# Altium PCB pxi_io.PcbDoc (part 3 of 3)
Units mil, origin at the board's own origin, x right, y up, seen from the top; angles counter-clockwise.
Board outline 6300 x 3935 mil, 2 copper layers (Top Layer, Bottom Layer); 271 components, 388 nets, 1544 pads, 249 vias.
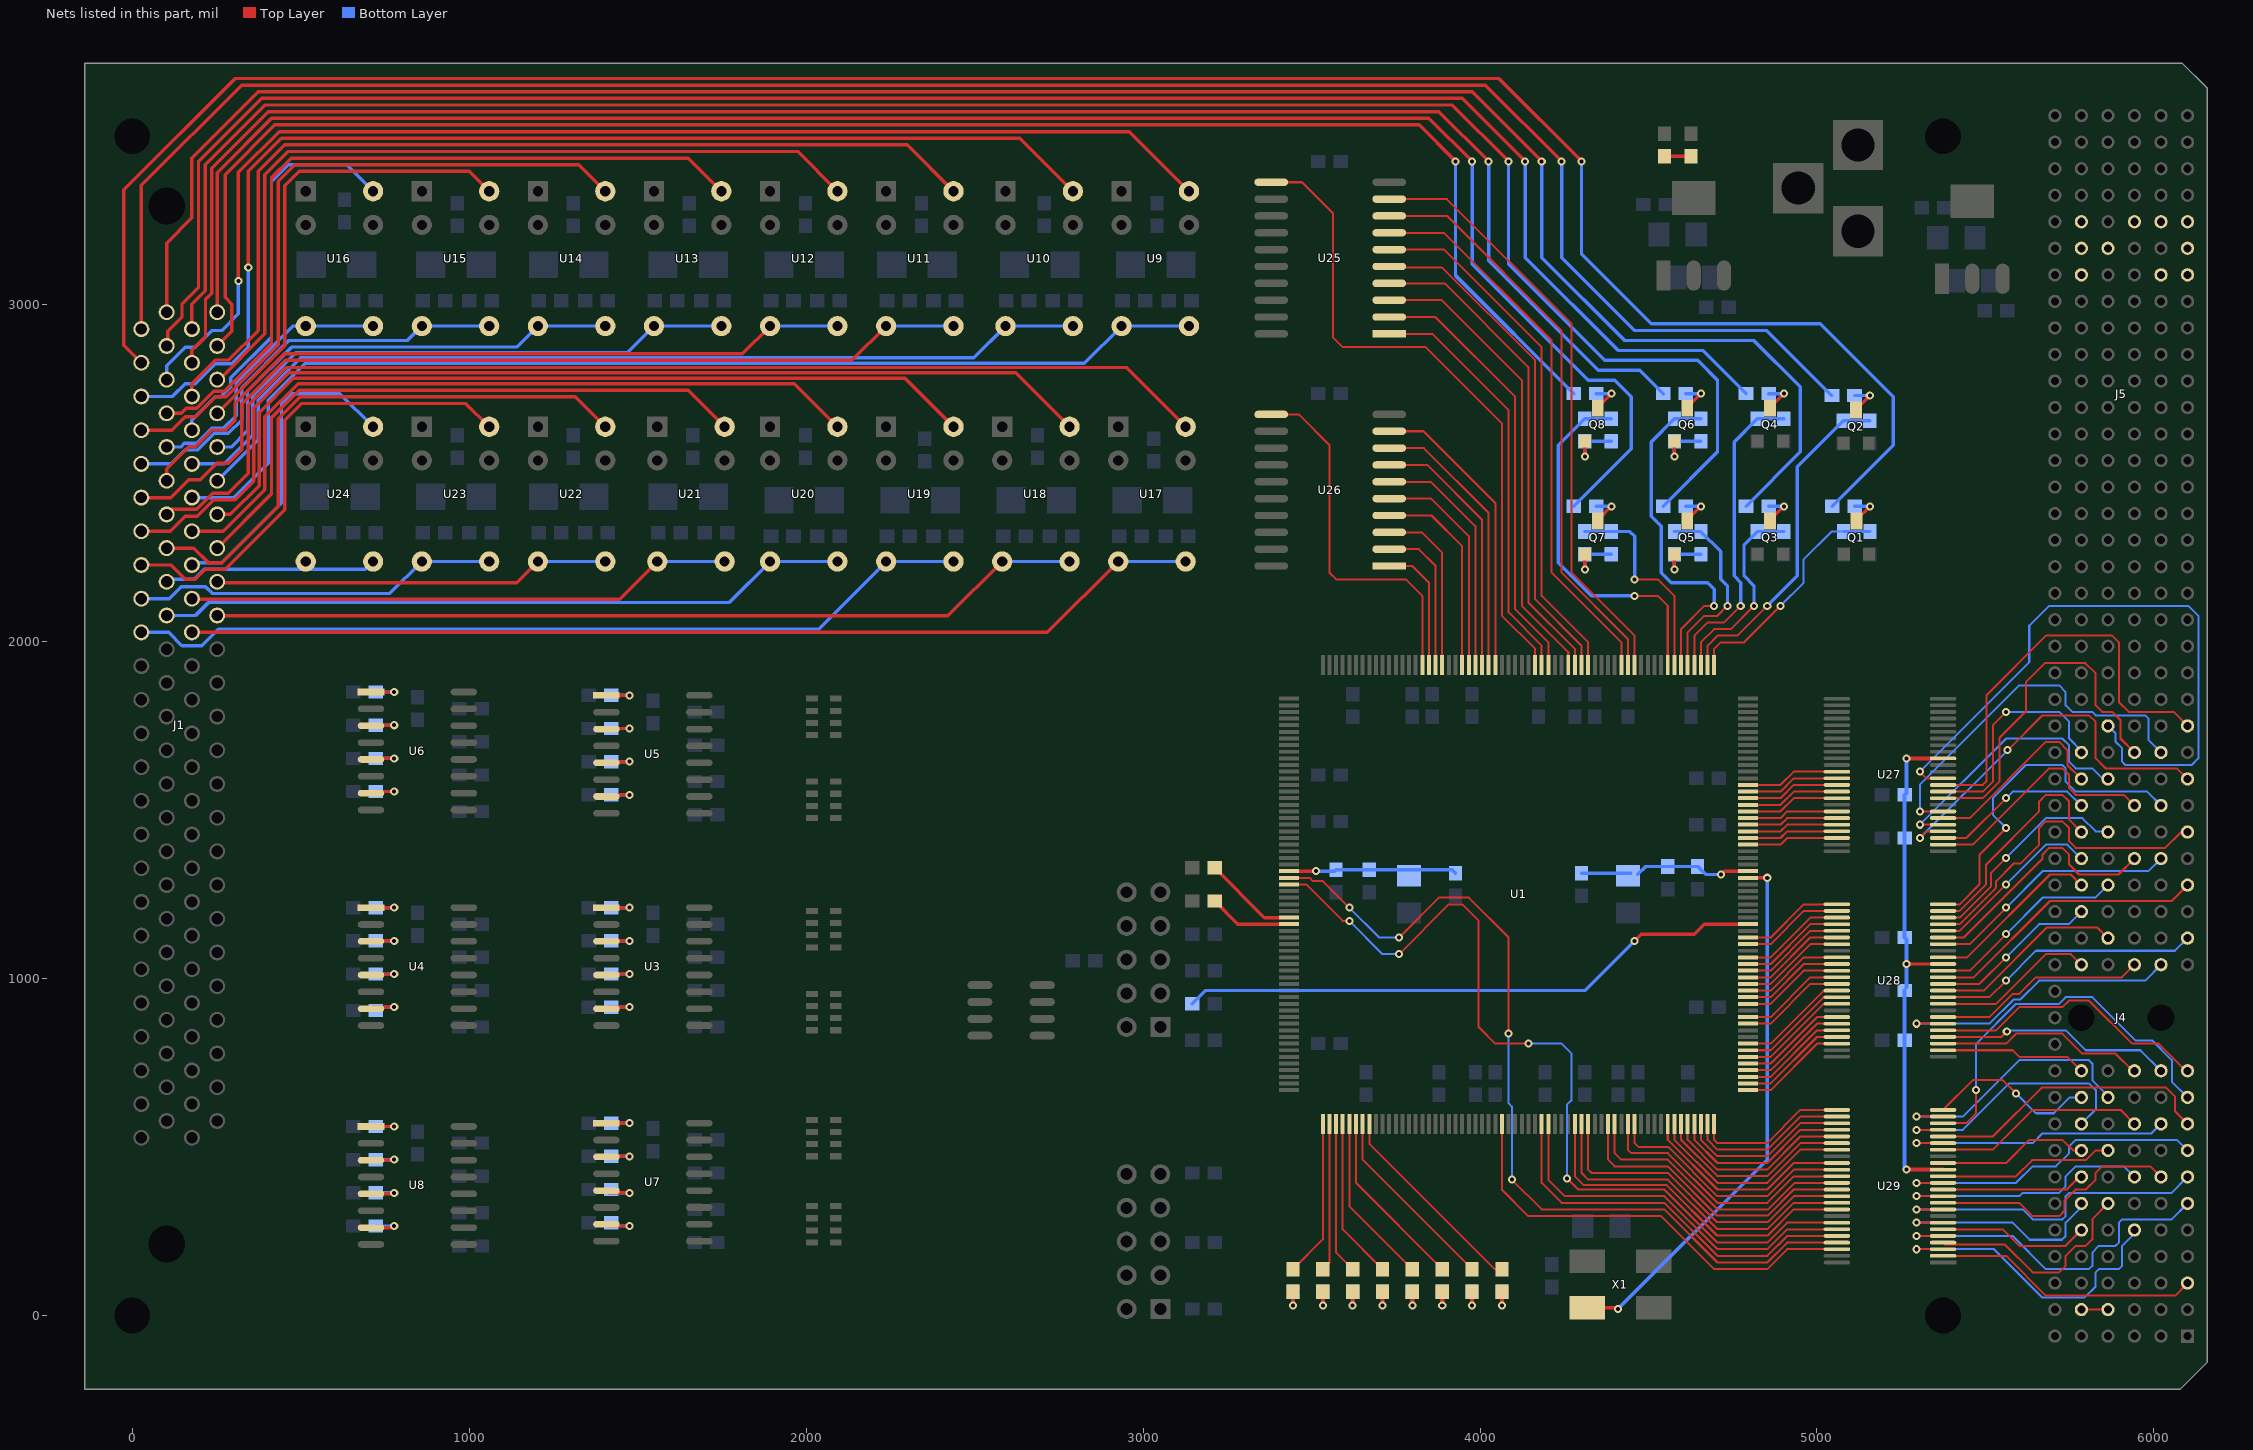
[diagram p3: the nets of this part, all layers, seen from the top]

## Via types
v1: diameter 24, hole 12, Top Layer to Bottom Layer, 241 vias
v2: diameter 36, hole 18, Top Layer to Bottom Layer, 7 vias
v3: diameter 24, hole 12, Top Layer to Bottom Layer, tented bottom, 1 vias

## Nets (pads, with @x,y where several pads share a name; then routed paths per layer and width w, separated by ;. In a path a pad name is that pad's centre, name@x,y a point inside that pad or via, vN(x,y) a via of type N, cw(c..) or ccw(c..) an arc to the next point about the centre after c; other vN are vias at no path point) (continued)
NetC85_1: C85.1 Q5.2 R108.2 | length 169.6
  Top Layer w10: v1(4576.77,2214.57) 4576.77,2258.93 Q5.2@4577.63,2259.79
  Bottom Layer w10: v1(4576.77,2214.57) C85.1@4576.77,2259.84 R108.2@4655.51,2259.84
NetC86_1: C86.1 Q6.2 R110.2 | length 169.6
  Top Layer w10: v1(4576.77,2549.21) 4576.77,2593.57 Q6.2@4577.63,2594.43
  Bottom Layer w10: v1(4576.77,2549.21) C86.1@4576.77,2594.49 R110.2@4655.51,2594.49
NetC87_1: C87.1 Q7.2 R112.2 | length 169.6
  Top Layer w10: v1(4311.02,2214.57) 4311.02,2258.93 Q7.2@4311.88,2259.79
  Bottom Layer w10: v1(4311.02,2214.57) C87.1@4311.02,2259.84 R112.2@4389.76,2259.84
NetC88_1: C88.1 Q8.2 R114.2 | length 169.6
  Top Layer w10: v1(4311.02,2549.21) 4311.02,2593.57 Q8.2@4311.88,2594.43
  Bottom Layer w10: v1(4311.02,2549.21) C88.1@4311.02,2594.49 R114.2@4389.76,2594.49
NetDS1_1: DS1.1 U1.68 | length 606.5
  Top Layer w6: U1.68@3671.26,568.9 3671.26,510.39 4043.85,137.8 DS1.1@4064.96,137.8
NetDS1_2: DS1.2 R120.1 | length 82.7
  Top Layer w12: v1(4064.96,29.53) DS1.2@4064.96,70.87
  Bottom Layer w10: v1(4064.96,29.53) R120.1@4064.96,70.87
NetDS2_1: DS2.1 U1.67 | length 565.6
  Top Layer w6: U1.67@3651.57,568.9 3651.57,462.6 DS2.1@3976.38,137.8
NetDS2_2: DS2.2 R121.1 | length 82.7
  Top Layer w12: v1(3976.38,29.53) DS2.2@3976.38,70.87
  Bottom Layer w10: v1(3976.38,29.53) R121.1@3976.38,70.87
NetDS3_1: DS3.1 U1.66 | length 537.1
  Top Layer w6: U1.66@3631.89,568.9 3631.89,393.7 DS3.1@3887.8,137.8
NetDS3_2: DS3.2 R122.1 | length 82.7
  Top Layer w12: v1(3887.8,29.53) DS3.2@3887.8,70.87
  Bottom Layer w10: v1(3887.8,29.53) R122.1@3887.8,70.87
NetDS4_1: DS4.1 U1.65 | length 508.6
  Top Layer w6: U1.65@3612.2,568.9 3612.2,324.8 DS4.1@3799.21,137.8
NetDS4_2: DS4.2 R123.1 | length 82.7
  Top Layer w12: v1(3799.21,29.53) DS4.2@3799.21,70.87
  Bottom Layer w10: v1(3799.21,29.53) R123.1@3799.21,70.87
NetDS5_1: DS5.1 U1.64 | length 480
  Top Layer w6: U1.64@3592.52,568.9 3592.52,255.91 DS5.1@3710.63,137.8
NetDS5_2: DS5.2 R124.1 | length 82.7
  Top Layer w12: v1(3710.63,29.53) DS5.2@3710.63,70.87
  Bottom Layer w10: v1(3710.63,29.53) R124.1@3710.63,70.87
NetDS6_1: DS6.1 U1.63 | length 451.5
  Top Layer w6: U1.63@3572.83,568.9 3572.83,187.01 DS6.1@3622.05,137.8
NetDS6_2: DS6.2 R125.1 | length 82.7
  Top Layer w12: v1(3622.05,29.53) DS6.2@3622.05,70.87
  Bottom Layer w10: v1(3622.05,29.53) R125.1@3622.05,70.87
NetDS7_1: DS7.1 U1.62 | length 439.3
  Top Layer w6: DS7.1@3533.46,137.8 3553.15,157.48 U1.62@3553.15,568.9
NetDS7_2: DS7.2 R126.1 | length 82.7
  Top Layer w10: v1(3533.46,29.53) DS7.2@3533.46,70.87
  Bottom Layer w10: v1(3533.46,29.53) R126.1@3533.46,70.87
NetDS8_1: DS8.1 U1.61 | length 467.8
  Top Layer w6: DS8.1@3444.88,137.8 3533.46,226.38 U1.61@3533.46,568.9
NetDS8_2: DS8.2 R127.1 | length 82.7
  Top Layer w10: v1(3444.88,29.53) DS8.2@3444.88,70.87
  Bottom Layer w10: v1(3444.88,29.53) R127.1@3444.88,70.87
NetDS9_2: DS9.2 R140.2 | length 78.7
  Top Layer w10: R140.2@4547.24,3440.94 DS9.2@4625.98,3440.94
NetJ4_d2: J4.D2 J4.E2 | length 78.7
  Top Layer w6: J4.E2@5784.65,17.72 J4.D2@5863.39,17.72
NetQ1_1: Q1.1 R101.1 | length 105.4
  Top Layer w10: Q1.1@5117,2358.21 5117,2361.09 v1(5157.48,2401.57)
  Bottom Layer w10: R101.1@5112.2,2401.57 v1(5157.48,2401.57)
NetQ2_1: Q2.1 R103.1 | length 105.4
  Top Layer w10: Q2.1@5116.14,2687.01 5116.14,2689.89 v1(5156.62,2730.37)
  Bottom Layer w10: R103.1@5111.35,2730.37 v1(5156.62,2730.37)
NetQ3_1: Q3.1 R105.1 | length 105.4
  Top Layer w10: Q3.1@4861.09,2358.21 4861.09,2361.09 v1(4901.57,2401.57)
  Bottom Layer w10: R105.1@4856.3,2401.57 v1(4901.57,2401.57)
NetQ4_1: Q4.1 R107.1 | length 105.4
  Top Layer w10: Q4.1@4861.09,2692.86 4861.09,2695.74 v1(4901.57,2736.22)
  Bottom Layer w10: R107.1@4856.3,2736.22 v1(4901.57,2736.22)
NetQ5_1: Q5.1 R109.1 | length 105.4
  Top Layer w10: Q5.1@4615.03,2358.21 4615.03,2361.09 v1(4655.51,2401.57)
  Bottom Layer w10: R109.1@4610.24,2401.57 v1(4655.51,2401.57)
NetQ6_1: Q6.1 R111.1 | length 105.4
  Top Layer w10: Q6.1@4615.03,2692.86 4615.03,2695.74 v1(4655.51,2736.22)
  Bottom Layer w10: R111.1@4610.24,2736.22 v1(4655.51,2736.22)
NetQ7_1: Q7.1 R113.1 | length 101
  Top Layer w10: Q7.1@4350.39,2362.2 v1(4389.76,2401.57)
  Bottom Layer w10: R113.1@4344.49,2401.57 v1(4389.76,2401.57)
NetQ8_1: Q8.1 R115.1 | length 105.4
  Top Layer w10: Q8.1@4349.28,2692.86 4349.28,2695.74 v1(4389.76,2736.22)
  Bottom Layer w10: R115.1@4344.49,2736.22 v1(4389.76,2736.22)
NetR9_1: R9.1 U1.34 | length 281.6
  Top Layer w10: R9.1@3212.6,1328.74 3360.24,1181.1 U1.34@3433.07,1181.1
NetR10_1: R10.1 U1.35 | length 249
  Top Layer w10: R10.1@3212.6,1230.32 3281.5,1161.42 U1.35@3433.07,1161.42
NetR11_2: R11.2 U3.7 | length 126
  Top Layer w10: U3.7@1407.48,910.63 1412.2,915.35 v1(1476.38,915.35)
  Bottom Layer w10: R11.2@1421.26,915.35 v1(1476.38,915.35)
NetR12_2: R12.2 U3.5 | length 125.3
  Top Layer w10: U3.5@1407.48,1010.63 1410.63,1013.78 v1(1476.38,1013.78)
  Bottom Layer w10: R12.2@1421.26,1013.78 v1(1476.38,1013.78)
NetR13_2: R13.2 U3.3 | length 124.7
  Top Layer w10: U3.3@1407.48,1110.63 1409.05,1112.2 v1(1476.38,1112.2)
  Bottom Layer w10: R13.2@1421.26,1112.2 v1(1476.38,1112.2)
NetR14_2: R14.2 U3.1 | length 124
  Top Layer w10: U3.1@1407.48,1210.63 v1(1476.38,1210.63)
  Bottom Layer w10: R14.2@1421.26,1210.63 v1(1476.38,1210.63)
NetR19_2: R19.2 U4.7 | length 130
  Top Layer w10: U4.7@708.66,910.63 713.39,915.35 v1(777.56,915.35)
  Bottom Layer w10: R19.2@722.44,905.51 732.28,915.35 v1(777.56,915.35)
NetR20_2: R20.2 U4.5 | length 125.3
  Top Layer w10: U4.5@708.66,1010.63 711.81,1013.78 v1(777.56,1013.78)
  Bottom Layer w10: R20.2@722.44,1013.78 v1(777.56,1013.78)
NetR21_2: R21.2 U4.3 | length 124.7
  Top Layer w10: U4.3@708.66,1110.63 710.24,1112.2 v1(777.56,1112.2)
  Bottom Layer w10: R21.2@722.44,1112.2 v1(777.56,1112.2)
NetR22_2: R22.2 U4.1 | length 124
  Top Layer w10: U4.1@708.66,1210.63 v1(777.56,1210.63)
  Bottom Layer w10: R22.2@722.44,1210.63 v1(777.56,1210.63)
NetR27_2: R27.2 U5.7 | length 119.3
  Top Layer w10: U5.7@1412.2,1545.28 v1(1476.38,1545.28)
  Bottom Layer w10: R27.2@1421.26,1545.28 v1(1476.38,1545.28)
NetR28_2: R28.2 U5.5 | length 120.9
  Top Layer w10: U5.5@1410.63,1643.7 v1(1476.38,1643.7)
  Bottom Layer w10: R28.2@1421.26,1643.7 v1(1476.38,1643.7)
NetR29_2: R29.2 U5.3 | length 124.7
  Top Layer w10: U5.3@1407.48,1740.55 1409.06,1742.13 v1(1476.38,1742.13)
  Bottom Layer w10: R29.2@1421.26,1742.13 v1(1476.38,1742.13)
NetR30_2: R30.2 U5.1 | length 124
  Top Layer w10: U5.1@1407.48,1840.55 v1(1476.38,1840.55)
  Bottom Layer w10: R30.2@1421.26,1840.55 v1(1476.38,1840.55)
NetR35_2: R35.2 U6.7 | length 126
  Top Layer w10: U6.7@708.66,1550.39 713.39,1555.12 v1(777.56,1555.12)
  Bottom Layer w10: R35.2@722.44,1555.12 v1(777.56,1555.12)
NetR36_2: R36.2 U6.5 | length 125.3
  Top Layer w10: U6.5@708.66,1650.39 711.81,1653.54 v1(777.56,1653.54)
  Bottom Layer w10: R36.2@722.44,1653.54 v1(777.56,1653.54)
NetR37_2: R37.2 U6.3 | length 124.7
  Top Layer w10: U6.3@708.66,1750.39 710.24,1751.97 v1(777.56,1751.97)
  Bottom Layer w10: R37.2@722.44,1751.97 v1(777.56,1751.97)
NetR38_2: R38.2 U6.1 | length 124
  Top Layer w10: U6.1@708.66,1850.39 v1(777.56,1850.39)
  Bottom Layer w10: R38.2@722.44,1850.39 v1(777.56,1850.39)
NetR45_2: R45.2 U7.7 | length 130.2
  Top Layer w10: U7.7@1407.48,270.87 1412.6,265.75 v1(1476.38,265.75)
  Bottom Layer w10: R45.2@1421.26,275.59 1431.1,265.75 v1(1476.38,265.75)
NetR48_2: R48.2 U7.5 | length 130.9
  Top Layer w10: U7.5@1407.48,370.87 1414.17,364.17 v1(1476.38,364.17)
  Bottom Layer w10: R48.2@1421.26,374.02 1431.1,364.17 v1(1476.38,364.17)
NetR51_2: R51.2 U7.3 | length 124.7
  Top Layer w10: U7.3@1407.48,470.87 1409.06,472.44 v1(1476.38,472.44)
  Bottom Layer w10: R51.2@1421.26,472.44 v1(1476.38,472.44)
NetR54_2: R54.2 U7.1 | length 124
  Top Layer w10: U7.1@1407.48,570.87 v1(1476.38,570.87)
  Bottom Layer w10: R54.2@1421.26,570.87 v1(1476.38,570.87)
NetR61_2: R61.2 U8.7 | length 126
  Top Layer w10: U8.7@708.66,261.02 772.83,261.02 v1(777.56,265.75)
  Bottom Layer w10: R61.2@722.44,265.75 v1(777.56,265.75)
NetR64_2: R64.2 U8.5 | length 125.3
  Top Layer w10: U8.5@708.66,361.02 774.41,361.02 v1(777.56,364.17)
  Bottom Layer w10: R64.2@722.44,364.17 v1(777.56,364.17)
NetR67_2: R67.2 U8.3 | length 122.4
  Top Layer w10: U8.3@708.66,461.02 v1@775.98,461.02
  Bottom Layer w10: R67.2@722.44,462.6 v1(777.56,462.6)
NetR70_2: R70.2 U8.1 | length 124
  Top Layer w10: U8.1@708.66,561.02 v1(777.56,561.02)
  Bottom Layer w10: R70.2@722.44,561.02 v1(777.56,561.02)
NetU1_153: U1.153 X1.3 | length 1613
  Top Layer w10: X1.3@4317.98,23.1 4406.03,23.1 v1(4409.45,19.69) ; U1.153@4795.28,1299.21 v1(4852.36,1299.21)
  Bottom Layer w10: v1(4409.45,19.69) 4852.36,462.6 v1(4852.36,1299.21)
NSTATUS: R8.2 U1.146 | length 1747.5
  Top Layer w10: v1(4458.66,1112.2) 4478.35,1131.89 4635.83,1131.89 4665.35,1161.42 U1.146@4795.28,1161.42
  Bottom Layer w10: R8.2@3145.67,925.2 3185.04,964.57 4311.02,964.57 v1(4458.66,1112.2)
O5_1_A: J1.39 U9.5 U9.6 | length 3279.5
  Bottom Layer w10: J1.39@177.17,2427.56 301.57,2427.56 403.54,2529.53 403.54,2716.54 513.28,2826.28 2825.88,2826.28 U9.5@2936.22,2936.61 U9.6@3136.22,2936.61
O5_1_B: J1.96 U9.10 | length 3682.7
  Top Layer w10: v1(314.96,3070.87) 314.96,3392.73 436.01,3513.78 2959.06,3513.78 U9.10@3136.22,3336.61
  Bottom Layer w10: J1.96@102.17,2777.56 102.17,2818.7 157.48,2874.02 187.01,2874.02 236.22,2923.23 265.75,2923.23 314.96,2972.44 v1(314.96,3070.87)
O5_2_A: J1.40 U10.5 U10.6 | length 2798.3
  Bottom Layer w10: J1.40@252.17,2477.56 374.02,2599.41 374.02,2716.54 499.76,2842.28 2497.39,2842.28 U10.5@2591.73,2936.61 U10.6@2791.73,2936.61
O5_2_B: J1.95 U10.10 | length 3452.9
  Top Layer w10: v1(344.49,3110.24) 344.49,3395.67 442.91,3494.09 2634.25,3494.09 U10.10@2791.73,3336.61
  Bottom Layer w10: J1.95@27.17,2727.56 119.29,2727.56 157.48,2765.75 187.01,2765.75 246.06,2824.8 295.28,2824.8 344.49,2874.02 v1(344.49,3110.24)
O5_3_A: J1.89 U11.5 U11.6 | length 2700.7
  Top Layer w10: J1.89@27.17,2427.56 114.57,2427.56 167.32,2480.32 201.51,2480.32 250.72,2529.53 285.43,2529.53 324.8,2568.9 324.8,2704.77 454.68,2834.65 2135.43,2834.65 U11.5@2237.4,2936.61
  Bottom Layer w10: U11.5@2237.4,2936.61 U11.6@2437.4,2936.61
O5_3_B: J1.45 U11.10 | length 2925.8
  Top Layer w10: J1.45@177.17,2727.56 177.17,2765.75 247.44,2836.02 286.81,2836.02 374.02,2923.23 374.02,3395.67 452.76,3474.41 2299.61,3474.41 U11.10@2437.4,3336.61
O5_4_A: J1.90 U12.5 U12.6 | length 2231.4
  Top Layer w10: J1.90@102.17,2477.56 102.17,2513.58 167.32,2578.74 187.01,2578.74 236.22,2627.95 275.59,2627.95 305.12,2657.48 305.12,2707.71 451.74,2854.33 1810.63,2854.33 U12.5@1892.91,2936.61
  Bottom Layer w10: U12.5@1892.91,2936.61 U12.6@2092.91,2936.61
O5_4_B: J1.46 U12.10 | length 2446.9
  Top Layer w10: J1.46@252.17,2777.56 257.87,2777.56 393.7,2913.39 393.7,3385.83 462.6,3454.72 1974.8,3454.72 U12.10@2092.91,3336.61
O5_5_A: J1.41 U13.5 U13.6 | length 1809.9
  Bottom Layer w10: J1.41@177.17,2527.56 273.62,2527.56 358.02,2611.95 358.02,2730.06 486.23,2858.28 1470.09,2858.28 U13.5@1548.43,2936.61 U13.6@1748.43,2936.61
O5_5_B: J1.94 U13.10 | length 2289.1
  Top Layer w10: J1.94@102.17,2677.56 145.09,2677.56 160.47,2692.94 191.51,2692.94 241.51,2742.94 272.46,2742.94 413.39,2883.86 413.39,3375.98 472.44,3435.04 1650,3435.04 U13.10@1748.43,3336.61
O5_6_A: J1.42 U14.5 U14.6 | length 1369.7
  Bottom Layer w10: J1.42@252.17,2577.56 294.09,2577.56 342.02,2625.48 342.02,2743.59 472.7,2874.28 1141.6,2874.28 U14.5@1203.94,2936.61 U14.6@1403.94,2936.61
O5_6_B: J1.93 U14.10 | length 2019.9
  Top Layer w10: J1.93@27.17,2627.56 117.72,2627.56 157.48,2667.32 188.52,2667.32 247.57,2726.38 278.53,2726.38 433.07,2880.92 433.07,3366.14 482.28,3415.35 1325.2,3415.35 U14.10@1403.94,3336.61
O5_7_A: J1.91 U15.5 U15.6 | length 1258
  Bottom Layer w10: J1.91@27.17,2527.56 116.14,2527.56 157.48,2568.9 194.54,2568.9 243.75,2618.11 285.43,2618.11 324.8,2657.48 324.8,2753.5 465,2893.7 816.53,2893.7 U15.5@859.45,2936.61 U15.6@1059.45,2936.61
O5_7_B: J1.44 U15.10 | length 1407.6
  Top Layer w10: J1.44@252.25,2677.47 452.76,2877.97 452.76,3353.36 495.07,3395.67 1000.39,3395.67 U15.10@1059.45,3336.61
O5_8_A: J1.92 U16.5 U16.6 | length 819.2
  Bottom Layer w10: J1.92@102.17,2577.56 143.51,2577.56 154.54,2588.58 191.6,2588.58 237.13,2634.11 271.91,2634.11 308.8,2671.01 308.8,2769.43 475.98,2936.61 U16.5@514.96,2936.61 U16.6@714.96,2936.61
O5_8_B: J1.43 U16.10 | length 1177.5
  Bottom Layer w10: J1.43@177.17,2651.18 177.17,2657.48 246.06,2726.38 263.28,2726.38 292.8,2755.91 292.8,2782.96 413.39,2903.54 413.39,3366.14 462.6,3415.35 636.22,3415.35 U16.10@714.96,3336.61
O5_D1: U1.193 U25.9 | length 1784.1
  Top Layer w6: U25.9@3730.31,3313.39 3901.18,3313.39 4271.65,2942.91 4271.65,2204.72 4458.66,2017.72 U1.193@4458.66,1931.1
O5_D2: U1.194 U25.8 | length 1726.4
  Top Layer w6: U25.8@3730.31,3263.39 3901.97,3263.39 4242.13,2923.23 4242.13,2204.72 4438.98,2007.87 U1.194@4438.98,1931.1
O5_D3: U1.195 U25.7 | length 1662.9
  Top Layer w6: U25.7@3730.31,3213.39 3892.91,3213.39 4212.6,2893.7 4212.6,2204.72 4419.29,1998.03 U1.195@4419.29,1931.1
O5_D4: U1.200 U25.6 | length 1572.6
  Top Layer w6: U25.6@3730.31,3163.39 3893.7,3163.39 4183.07,2874.02 4183.07,2135.83 4320.87,1998.03 U1.200@4320.87,1931.1
O5_D5: U1.201 U25.5 | length 1509.1
  Top Layer w6: U25.5@3730.31,3113.39 3733.46,3110.24 3887.8,3110.24 4163.39,2834.65 4163.39,2125.98 4301.18,1988.19 U1.201@4301.18,1931.1
O5_D6: U1.202 U25.4 | length 1457.2
  Top Layer w6: U25.4@3730.31,3063.39 3895.28,3063.39 4143.7,2814.96 4143.7,2116.14 4281.5,1978.35 U1.202@4281.5,1931.1
O5_D7: U1.203 U25.3 | length 1393.8
  Top Layer w6: U25.3@3730.31,3013.39 3886.22,3013.39 4124.02,2775.59 4124.02,2106.3 4261.81,1968.5 U1.203@4261.81,1931.1
O5_D8: U1.206 U25.2 | length 1308.2
  Top Layer w6: U25.2@3730.31,2963.39 3867.32,2963.39 4104.33,2726.38 4104.33,2096.46 4202.76,1998.03 U1.206@4202.76,1931.1
O5_LE: U1.208 U25.11 | length 1954.3
  Top Layer w6: U25.11@3380.31,3363.39 3471.65,3363.39 3562.99,3272.05 3562.99,2903.54 3592.52,2874.02 3838.58,2874.02 4064.96,2647.64 4064.96,2076.77 4163.39,1978.35 U1.208@4163.39,1931.1
O5_OE: U1.207 U25.1 | length 1244.8
  Top Layer w6: U25.1@3730.31,2913.39 3858.27,2913.39 4084.65,2687.01 4084.65,2086.61 4183.07,1988.19 U1.207@4183.07,1931.1
O27_1_A: J1.31 U17.5 U17.6 | length 3012.7
  Top Layer w10: J1.31@200.79,2027.56 2716.14,2027.56 U17.5@2926.38,2237.8
  Bottom Layer w10: U17.5@2926.38,2237.8 U17.6@3126.38,2237.8
O27_1_B: J1.88 U17.10 | length 3396
  Top Layer w10: J1.88@102.17,2377.56 117.54,2392.94 191.51,2392.94 239.51,2440.94 285.43,2440.94 344.49,2500 344.49,2701.82 456.41,2813.75 2950.43,2813.75 U17.10@3126.38,2637.8
O27_2_A: J1.32 U18.5 U18.6 | length 2596.4
  Top Layer w10: J1.32@252.17,2076.77 2420.87,2076.77 U18.5@2581.89,2237.8
  Bottom Layer w10: U18.5@2581.89,2237.8 U18.6@2781.89,2237.8
O27_2_B: J1.87 U18.10 | length 3142.6
  Top Layer w10: J1.87@27.17,2327.56 112.99,2327.56 157.48,2372.05 193.24,2372.05 242.46,2421.26 305.12,2421.26 360.49,2476.63 360.49,2693.17 465.07,2797.75 2621.94,2797.75 U18.10@2781.89,2637.8
O27_3_A: J1.81 U19.5 U19.6 | length 2529.9
  Bottom Layer w10: J1.81@27.17,2027.56 108.27,2027.56 147.64,1988.19 206.69,1988.19 255.91,2037.4 2037.01,2037.4 U19.5@2237.4,2237.8 U19.6@2437.4,2237.8
O27_3_B: J1.38 U19.10 | length 2539.1
  Top Layer w10: J1.38@252.17,2377.56 290.94,2377.56 376.49,2463.1 376.49,2679.64 478.6,2781.75 2293.45,2781.75 U19.10@2437.4,2637.8
O27_4_A: J1.82 U20.5 U20.6 | length 2057.1
  Bottom Layer w10: J1.82@102.17,2077.56 187.8,2077.56 226.38,2116.14 1771.26,2116.14 U20.5@1892.91,2237.8 U20.6@2092.91,2237.8
O27_4_B: J1.37 U20.10 | length 2277.1
  Top Layer w10: J1.37@177.17,2327.56 270.47,2327.56 393.7,2450.79 393.7,2667.32 492.13,2765.75 1964.96,2765.75 U20.10@2092.91,2637.8
O27_5_A: J1.33 U21.5 U21.6 | length 1627.4
  Top Layer w10: J1.33@177.17,2125.98 1446.46,2125.98 U21.5@1558.27,2237.8
  Bottom Layer w10: U21.5@1558.27,2237.8 U21.6@1758.27,2237.8
O27_5_B: J1.36 U21.10 | length 1877.2
  Top Layer w10: J1.36@252.17,2277.56 413.39,2438.78 413.39,2664.38 495.07,2746.06 1650,2746.06 U21.10@1758.27,2637.8
O27_6_A: J1.34 U22.5 U22.6 | length 1151.7
  Top Layer w10: 278.15,2175.2 1141.34,2175.2 U22.5@1203.94,2237.8
  Bottom Layer w10: U22.5@1203.94,2237.8 U22.6@1403.94,2237.8
O27_6_B: J1.86 U22.10 | length 1712.5
  Top Layer w10: J1.86@102.17,2277.56 183.07,2277.56 226.38,2234.25 265.75,2234.25 433.07,2401.57 433.07,2661.44 498.01,2726.38 1315.35,2726.38 U22.10@1403.94,2637.8
O27_7_A: J1.83 U23.5 U23.6 | length 1094.7
  Bottom Layer w10: J1.83@27.17,2127.56 109.84,2127.56 145.5,2163.22 217.54,2163.22 237.82,2142.94 764.59,2142.94 U23.5@859.45,2237.8 U23.6@1059.45,2237.8
O27_7_B: J1.85 U23.10 | length 1450.2
  Top Layer w10: J1.85@27.17,2227.56 114.96,2227.56 157.48,2185.04 187.01,2185.04 216.54,2214.57 275.59,2214.57 452.76,2391.73 452.76,2657.48 501.97,2706.69 990.55,2706.69 U23.10@1059.45,2637.8
O27_8_A: J1.84 U24.5 U24.6 | length 637.7
  Bottom Layer w10: J1.84@102.17,2177.56 109.65,2185.04 183.61,2185.04 213.14,2214.57 691.73,2214.57 U24.6@714.96,2237.8
O27_8_B: J1.35 U24.10 | length 952.8
  Bottom Layer w10: J1.35@183.86,2234.25 265.75,2234.25 442.91,2411.42 442.91,2706.69 472.44,2736.22 616.54,2736.22 U24.10@714.96,2637.8
O27_D1: U1.214 U26.9 | length 883.5
  Top Layer w6: U26.9@3730.31,2624.41 3832.28,2624.41 4045.28,2411.42 U1.214@4045.28,1931.1
O27_D2: U1.215 U26.8 | length 825.8
  Top Layer w6: U26.8@3730.31,2574.41 3833.07,2574.41 4025.59,2381.89 U1.215@4025.59,1931.1
O27_D3: U1.216 U26.7 | length 773.9
  Top Layer w6: U26.7@3730.31,2524.41 3843.7,2524.41 4005.91,2362.2 U1.216@4005.91,1931.1
O27_D4: U1.217 U26.6 | length 722
  Top Layer w6: U26.6@3730.31,2474.41 3854.33,2474.41 3986.22,2342.52 U1.217@3986.22,1931.1
O27_D5: U1.218 U26.5 | length 664.3
  Top Layer w6: U26.5@3730.31,2424.41 3855.12,2424.41 3966.54,2312.99 U1.218@3966.54,1931.1
O27_D6: U1.219 U26.4 | length 606.6
  Top Layer w6: U26.4@3730.31,2374.41 3855.91,2374.41 3946.85,2283.46 U1.219@3946.85,1931.1
O27_D7: U1.222 U26.3 | length 515.3
  Top Layer w6: U26.3@3730.31,2324.41 3827.17,2324.41 3887.8,2263.78 U1.222@3887.8,1931.1
O27_D8: U1.223 U26.2 | length 451.8
  Top Layer w6: U26.2@3730.31,2274.41 3818.11,2274.41 3868.11,2224.41 U1.223@3868.11,1931.1
O27_LE: U1.225 U26.11 | length 1097.9
  Top Layer w6: U26.11@3380.31,2674.41 3461.81,2674.41 3553.15,2583.07 3553.15,2204.72 3572.83,2185.04 3779.53,2185.04 3828.74,2135.83 U1.225@3828.74,1931.1
O27_OE: U1.224 U26.1 | length 382.6
  Top Layer w6: U26.1@3730.31,2224.41 3799.21,2224.41 3848.43,2175.2 U1.224@3848.43,1931.1
OC5_1: J1.97 R101.2 | length 6876.1
  Top Layer w10: J1.97@27.17,2827.56 -25.2,2879.92 -25.2,3340.94 305.12,3671.26 4055.12,3671.26 v1(4301.18,3425.2)
  Bottom Layer w10: v1(4301.18,3425.2) 4301.18,3149.61 4507.87,2942.91 5009.84,2942.91 5226.38,2726.38 5226.38,2582.68 R101.2@5045.28,2401.57
OC5_2: J1.99 R103.2 | length 6092.1
  Top Layer w10: J1.99@27.17,2951.18 27.17,3353.94 324.8,3651.57 4015.75,3651.57 v1(4242.13,3425.2)
  Bottom Layer w10: v1(4242.13,3425.2) 4242.13,3139.76 4458.66,2923.23 4851.56,2923.23 R103.2@5044.42,2730.37
OC5_3: J1.100 R105.2 | length 6271.3
  Top Layer w10: J1.100@102.17,3001.18 102.17,3182.87 177.17,3257.87 177.17,3435.04 374.02,3631.89 3976.38,3631.89 v1(4183.07,3425.2)
  Bottom Layer w10: v1(4183.07,3425.2) 4183.07,3139.76 4429.13,2893.7 4812.99,2893.7 4950.79,2755.91 4950.79,2562.99 R105.2@4789.37,2401.57
OC5_4: J1.98 R107.2 | length 5761.7
  Top Layer w10: 105.91,2901.18 105.91,2920.87 147.64,2962.6 147.64,3001.97 196.85,3051.18 196.85,3425.2 383.86,3612.2 3946.85,3612.2 v1(4133.86,3425.2)
  Bottom Layer w10: v1(4133.86,3425.2) 4133.86,3139.76 4409.45,2864.17 4661.42,2864.17 R107.2@4789.37,2736.22
OC5_5: J1.49 R109.2 | length 6000
  Top Layer w10: J1.49@177.17,2951.18 177.17,3001.97 216.54,3041.34 216.54,3415.35 393.7,3592.52 3917.32,3592.52 v1(4084.65,3425.2)
  Bottom Layer w10: v1(4084.65,3425.2) 4084.65,3120.08 4370.08,2834.65 4645.67,2834.65 4704.72,2775.59 4704.72,2562.99 R109.2@4543.31,2401.57
OC5_6: J1.47 R111.2 | length 5475.9
  Top Layer w10: 178,2852.02 177.17,2851.18 177.17,2864.17 217.54,2904.55 217.54,3015.52 236.17,3034.14 236.17,3398.56 236.22,3398.61 236.22,3405.51 403.54,3572.83 3877.95,3572.83 v1(4025.59,3425.2)
  Bottom Layer w10: v1(4025.59,3425.2) 4025.59,3129.92 4350.39,2805.12 4474.41,2805.12 R111.2@4543.31,2736.22
OC5_7: J1.50 R113.2 | length 5594.7
  Top Layer w10: J1.50@252.17,2977.56 252.17,3391.93 413.39,3553.15 3848.43,3553.15 v1(3976.38,3425.2)
  Bottom Layer w10: v1(3976.38,3425.2) 3976.38,3120.08 4320.87,2775.59 4399.61,2775.59 4448.82,2726.38 4448.82,2572.83 R113.2@4277.56,2401.57
OC5_8: J1.48 R115.2 | length 5126
  Top Layer w10: J1.48@252.17,2877.56 295.28,2920.67 295.28,3001.97 275.59,3021.65 275.59,3385.83 423.23,3533.46 3818.9,3533.46 v1(3927.17,3425.2)
  Bottom Layer w10: v1(3927.17,3425.2) 3927.17,3086.61 R115.2@4277.56,2736.22
OC5_D1: C81.2 R100.1 U1.181 | length 694.5
  Top Layer w6: U1.181@4694.88,1931.1 4694.88,1978.35 4714.57,1998.03 4783.46,1998.03 v1(4891.73,2106.3)
  Bottom Layer w6: v1(4891.73,2106.3) 4960.63,2175.2 4960.63,2244.09 5043.31,2326.77 C81.2@5078.74,2326.77
  Bottom Layer w10: C81.2@5078.74,2326.77 R100.1@5157.48,2326.77
OC5_D2: C82.2 R102.1 U1.182 | length 1004.6
  Top Layer w6: U1.182@4675.2,1931.1 4675.2,1988.19 4704.72,2017.72 4763.78,2017.72 v1(4852.36,2106.3)
  Bottom Layer w10: v1(4852.36,2106.3) 4940.94,2194.88 4940.94,2518.63 C82.2@5077.88,2655.57 R102.1@5156.62,2655.57
OC5_D3: C83.2 R104.1 U1.183 | length 597
  Top Layer w6: U1.183@4655.51,1931.1 4655.51,1998.03 4694.88,2037.4 4744.09,2037.4 v1(4812.99,2106.3)
  Bottom Layer w10: v1(4812.99,2106.3) 4812.99,2165.35 4783.46,2194.88 4783.46,2287.4 C83.2@4822.83,2326.77 R104.1@4901.57,2326.77
OC5_D4: C84.2 R106.1 U1.184 | length 931.7
  Top Layer w6: U1.184@4635.83,1931.1 4635.83,2017.72 4675.2,2057.09 4724.41,2057.09 v1(4773.62,2106.3)
  Bottom Layer w10: v1(4773.62,2106.3) 4773.62,2175.2 4753.94,2194.88 4753.94,2592.52 C84.2@4822.83,2661.42 R106.1@4901.57,2661.42
OC5_D5: C85.2 R108.1 U1.185 | length 579
  Top Layer w6: U1.185@4616.14,1931.1 4616.14,2027.56 4665.35,2076.77 4704.72,2076.77 v1(4734.25,2106.3)
  Bottom Layer w10: C85.2@4576.77,2326.77 R108.1@4655.51,2326.77 4714.57,2267.72 4714.57,2185.04 4734.25,2165.35 v1(4734.25,2106.3)
OC5_D6: C86.2 R110.1 U1.186 | length 1036.5
  Top Layer w6: U1.186@4596.46,1931.1 4596.46,2037.4 4665.35,2106.3 v1(4694.88,2106.3)
  Bottom Layer w10: R110.1@4655.51,2661.42 C86.2@4576.77,2661.42 4507.87,2592.52 4507.87,2372.05 4537.4,2342.52 4537.4,2204.72 4566.93,2175.2 4675.2,2175.2 4694.88,2155.51 v1(4694.88,2106.3)
OC5_D7: C87.2 R112.1 U1.187 | length 624.5
  Top Layer w6: v1(4458.66,2185.04) 4527.56,2185.04 4576.77,2135.83 U1.187@4576.77,1931.1
  Bottom Layer w10: C87.2@4311.02,2326.77 R112.1@4389.76,2326.77 4444.88,2326.77 4458.66,2312.99 v1(4458.66,2185.04)
OC5_D8: C88.2 R114.1 U1.188 | length 1091.5
  Top Layer w6: v1(4458.66,2135.83) 4527.56,2135.83 4557.09,2106.3 U1.188@4557.09,1931.1
  Bottom Layer w10: R114.1@4389.76,2661.42 C88.2@4311.02,2661.42 4232.28,2582.68 4232.28,2234.25 4330.71,2135.83 v1(4458.66,2135.83)
P_AD0: U1.167 U27.36 | length 280.1
  Top Layer w6: U1.167@4795.28,1574.8 4891.73,1574.8 4931.1,1614.17 U27.36@5059.06,1614.17
P_AD1: U1.166 U27.37 | length 280.1
  Top Layer w6: U1.166@4795.28,1555.12 4891.73,1555.12 4931.1,1594.49 U27.37@5059.06,1594.49
P_AD2: U1.165 U27.38 | length 280.1
  Top Layer w6: U1.165@4795.28,1535.43 4891.73,1535.43 4931.1,1574.8 U27.38@5059.06,1574.8
P_AD3: U1.164 U27.39 | length 280.1
  Top Layer w6: U1.164@4795.28,1515.75 4891.73,1515.75 4931.1,1555.12 U27.39@5059.06,1555.12
P_AD4: U1.163 U27.40 | length 280.1
  Top Layer w6: U1.163@4795.28,1496.06 4891.73,1496.06 4931.1,1535.43 U27.40@5059.06,1535.43
P_AD5: U1.162 U27.42 | length 271.9
  Top Layer w6: U1.162@4795.28,1476.38 4891.73,1476.38 4911.42,1496.06 U27.42@5059.06,1496.06
P_AD6: U1.161 U27.43 | length 271.9
  Top Layer w6: U1.161@4795.28,1456.69 4891.73,1456.69 4911.42,1476.38 U27.43@5059.06,1476.38
P_AD7: U1.160 U27.44 | length 271.9
  Top Layer w6: U1.160@4795.28,1437.01 4891.73,1437.01 4911.42,1456.69 U27.44@5059.06,1456.69
P_AD8: U1.158 U27.46 | length 271.9
  Top Layer w6: U1.158@4795.28,1397.64 4891.73,1397.64 4911.42,1417.32 U27.46@5059.06,1417.32
P_AD9: U1.144 U28.25 | length 304.5
  Top Layer w6: U1.144@4795.28,1122.05 4862.2,1122.05 4960.63,1220.47 U28.25@5059.06,1220.47
P_AD10: U1.143 U28.26 | length 304.5
  Top Layer w6: U1.143@4795.28,1102.36 4862.2,1102.36 4960.63,1200.79 U28.26@5059.06,1200.79
P_AD11: U1.141 U28.27 | length 312.7
  Top Layer w6: U1.141@4795.28,1062.99 4862.2,1062.99 4980.31,1181.1 U28.27@5059.06,1181.1
P_AD12: U1.140 U28.28 | length 312.7
  Top Layer w6: U1.140@4795.28,1043.31 4862.2,1043.31 4980.31,1161.42 U28.28@5059.06,1161.42
P_AD13: U1.139 U28.29 | length 312.7
  Top Layer w6: U1.139@4795.28,1023.62 4862.2,1023.62 4980.31,1141.73 U28.29@5059.06,1141.73
P_AD14: U1.138 U28.30 | length 312.7
  Top Layer w6: U1.138@4795.28,1003.94 4862.2,1003.94 4980.31,1122.05 U28.30@5059.06,1122.05
P_AD15: U1.137 U28.31 | length 312.7
  Top Layer w6: U1.137@4795.28,984.25 4862.2,984.25 4980.31,1102.36 U28.31@5059.06,1102.36
P_AD16: U1.122 U28.45 | length 320.9
  Top Layer w6: U1.122@4795.28,688.98 4862.2,688.98 5000,826.77 U28.45@5059.06,826.77
P_AD17: U1.123 U28.44 | length 320.9
  Top Layer w6: U1.123@4795.28,708.66 4862.2,708.66 5000,846.46 U28.44@5059.06,846.46
P_AD18: U1.124 U28.43 | length 320.9
  Top Layer w6: U1.124@4795.28,728.35 4862.2,728.35 5000,866.14 U28.43@5059.06,866.14
P_AD19: U1.120 U29.25 | length 456.3
  Top Layer w6: U1.120@4694.88,568.9 4694.88,521.65 4704.72,511.81 4852.36,511.81 4950.79,610.24 U29.25@5059.06,610.24
P_AD20: U1.119 U29.26 | length 484.4
  Top Layer w6: U1.119@4675.2,568.9 4675.2,521.22 4704.29,492.13 4852.36,492.13 4950.79,590.55 U29.26@5059.06,590.55
P_AD21: U1.118 U29.27 | length 511.2
  Top Layer w6: U1.118@4655.51,568.9 4655.51,521.22 4703.06,473.67 4853.59,473.67 4950.79,570.87 U29.27@5059.06,570.87
P_AD22: U1.117 U29.28 | length 539.8
  Top Layer w6: U1.117@4635.83,568.9 4635.83,521.65 4704.72,452.76 4852.36,452.76 4950.79,551.18 U29.28@5059.06,551.18
P_AD23: U1.116 U29.29 | length 567.9
  Top Layer w6: U1.116@4616.14,568.9 4616.14,521.22 4704.29,433.07 4852.36,433.07 4950.79,531.5 U29.29@5059.06,531.5
P_AD24: U1.113 U29.33 | length 643
  Top Layer w6: U1.113@4557.09,568.9 4557.09,521.65 4704.72,374.02 4852.36,374.02 4931.1,452.76 U29.33@5059.06,452.76
P_AD25: U1.108 U29.34 | length 755.3
  Top Layer w6: U1.108@4458.66,568.9 4458.66,511.81 4469.92,500.55 4558.07,500.55 4704.29,354.33 4852.36,354.33 4931.1,433.07 U29.34@5059.06,433.07
P_AD26: U1.107 U29.35 | length 794.7
  Top Layer w6: U1.107@4438.98,568.9 4438.98,492.13 4448.82,482.28 4557.09,482.28 4704.72,334.65 4852.36,334.65 4931.1,413.39 U29.35@5059.06,413.39
P_AD27: U1.105 U29.36 | length 848
  Top Layer w6: U1.105@4399.61,568.9 4399.61,482.28 4419.29,462.6 4557.09,462.6 4704.72,314.96 4854.76,314.96 4933.5,393.7 U29.36@5059.06,393.7
P_AD28: U1.104 U29.37 | length 886.2
  Top Layer w6: U1.104@4379.92,568.9 4379.92,462.6 4399.61,442.91 4557.09,442.91 4703.31,296.69 4853.78,296.69 4931.1,374.02 U29.37@5059.06,374.02
P_AD29: U1.101 U29.38 | length 970.7
  Top Layer w6: U1.101@4320.87,568.9 4320.87,433.07 4330.71,423.23 4557.09,423.23 4703.31,277.01 4853.78,277.01 4931.1,354.33 U29.38@5059.06,354.33
P_AD30: U1.100 U29.39 | length 1004.3
  Top Layer w6: U1.100@4301.18,568.9 4301.18,423.23 4320.87,403.54 4557.09,403.54 4703.31,257.32 4853.78,257.32 4931.1,334.65 U29.39@5059.06,334.65
P_AD31: U1.99 U29.40 | length 1037.9
  Top Layer w6: U1.99@4281.5,568.9 4281.5,413.39 4306.81,388.07 4552.87,388.07 4703.31,237.64 4853.78,237.64 4931.1,314.96 U29.40@5059.06,314.96
P_CBE0: U1.159 U27.45 | length 271.9
  Top Layer w6: U1.159@4795.28,1417.32 4891.73,1417.32 4911.42,1437.01 U27.45@5059.06,1437.01
P_CBE1: U1.136 U28.33 | length 304.5
  Top Layer w6: U1.136@4795.28,964.57 4862.2,964.57 4960.63,1062.99 U28.33@5059.06,1062.99
P_CBE2: U1.121 U28.46 | length 320.9
  Top Layer w6: U1.121@4795.28,669.29 4862.2,669.29 5000,807.09 U28.46@5059.06,807.09
P_CBE3: U1.114 U29.31 | length 623.3
  Top Layer w6: U1.114@4576.77,568.9 4576.77,521.65 4704.72,393.7 4852.36,393.7 4950.79,492.13 U29.31@5059.06,492.13
P_CLK: U1.29 U29.42 | length 2633.2
  Top Layer w6: U1.29@3433.07,1279.53 3484.25,1279.53 3592.52,1171.26 v1(3612.2,1171.26) ; v1(3759.84,1072.83) 3907.48,1220.47 3946.85,1220.47 3996.06,1171.26 3996.06,856.3 4045.28,807.09 v1(4143.7,807.09) ; v1(4258.6,406.76) 4291.34,374.02 4547.24,374.02 4704.72,216.54 4852.36,216.54 4911.42,275.59 U29.42@5059.06,275.59
  Bottom Layer w6: v1(3612.2,1171.26) 3710.63,1072.83 v1(3759.84,1072.83) ; v1(4143.7,807.09) 4242.13,807.09 4271.65,777.56 4271.65,639.76 4258.6,626.71 v1(4258.6,406.76)
P_DEVSEL: U1.128 U28.38 | length 329
  Top Layer w6: U1.128@4795.28,807.09 4862.2,807.09 5019.68,964.57 U28.38@5059.06,964.57
P_FRAME: U1.125 U28.42 | length 320.9
  Top Layer w6: U1.125@4795.28,748.03 4862.2,748.03 5000,885.83 U28.42@5059.06,885.83
P_GNT: U1.94 U29.44 | length 1165.3
  Top Layer w6: U1.94@4183.07,568.9 4183.07,393.7 4242.13,334.65 4547.24,334.65 4704.72,177.17 4852.36,177.17 4911.42,236.22 U29.44@5059.06,236.22
P_IDSEL: U1.115 U29.30 | length 594.4
  Top Layer w6: U1.115@4596.46,568.9 4596.46,521.65 4703.49,414.62 4853.59,414.62 4950.79,511.81 U29.30@5059.06,511.81
P_INTA: U1.88 U29.46 | length 1313.3
  Top Layer w6: U1.88@4064.96,568.9 4064.96,374.02 4143.7,295.28 4537.4,295.28 4694.88,137.8 4852.36,137.8 4911.42,196.85 U29.46@5059.06,196.85 U29.46@5057.64,195.43
P_IRDY: U1.126 U28.40 | length 329
  Top Layer w6: U1.126@4795.28,767.72 4862.2,767.72 5019.68,925.2 U28.40@5059.06,925.2
P_PAR: U1.135 U28.34 | length 304.5
  Top Layer w6: U1.135@4795.28,944.88 4862.2,944.88 4960.63,1043.31 U28.34@5059.06,1043.31
P_PERR: U1.132 U28.36 | length 312.7
  Top Layer w6: U1.132@4795.28,885.83 4862.2,885.83 4980.31,1003.94 U28.36@5059.06,1003.94
P_REQ: U1.95 U29.43 | length 1131.7
  Top Layer w6: U1.95@4202.76,568.9 4202.76,403.54 4251.97,354.33 4547.24,354.33 4704.72,196.85 4852.36,196.85 4911.42,255.91 U29.43@5059.06,255.91
P_RST: U1.28 U29.45 | length 2636.3
  Top Layer w6: U1.28@3433.07,1299.21 3494.09,1299.21 3503.94,1289.37 3533.46,1289.37 v1(3612.2,1210.63) ; v1@3759.84,1122.05 3877.95,1240.16 3966.54,1240.16 4084.65,1122.05 v1(4084.65,836.61) ; v1(4094.49,403.54) 4183.07,314.96 4547.24,314.96 4704.72,157.48 4852.36,157.48 4911.42,216.54 U29.45@5059.06,216.54
  Bottom Layer w6: v1(3612.2,1210.63) 3700.85,1121.99 v1(3759.78,1121.99) ; v1(4084.65,836.61) 4084.65,629.92 4094.49,620.08 v1(4094.49,403.54)
P_SERR: U1.134 U28.35 | length 304.5
  Top Layer w6: U1.134@4795.28,925.2 4862.2,925.2 4960.63,1023.62 U28.35@5059.06,1023.62
P_STOP: U1.131 U28.37 | length 312.7
  Top Layer w6: U1.131@4795.28,866.14 4862.2,866.14 4980.31,984.25 U28.37@5059.06,984.25
P_TRDY: U1.127 U28.39 | length 329
  Top Layer w6: U1.127@4795.28,787.4 4862.2,787.4 5019.68,944.88 U28.39@5059.06,944.88
PXI_AD0: J4.D24 U27.12 | length 1968.9
  Top Layer w6: v1(5305.12,1614.17) 5324.8,1594.49 U27.12@5374.02,1594.49
  Bottom Layer w6: v1(5305.12,1614.17) 5629.92,1938.98 5629.92,2047.24 5688.98,2106.3 6102.36,2106.3 6131.89,2076.77 6131.89,1653.54 6112.2,1633.86 5915.35,1633.86 5905.51,1643.7 5905.51,1683.07 5885.83,1702.76 5885.83,1727.56 J4.D24@5863.39,1750
PXI_AD1: J4.A24 U27.11 | length 1273.6
  Top Layer w6: U27.11@5374.02,1574.8 5492.13,1574.8 5502.95,1585.63 5502.95,1841.54 5679.13,2017.72 5875.98,2017.72 5895.67,1998.03 5895.67,1820.87 5925.2,1791.34 6058.27,1791.34 J4.A24@6099.61,1750
PXI_AD2: J4.E23 U27.10 | length 687.8
  Top Layer w6: U27.10@5374.02,1555.12 5492.13,1555.12 5521.65,1584.65 5521.65,1751.97 v1(5561.02,1791.34)
  Bottom Layer w6: v1(5561.02,1791.34) 5718.5,1791.34 5748.03,1761.81 5748.03,1712.6 5784.65,1675.98 J4.E23@5784.65,1671.26
PXI_AD3: J4.C23 U27.9 | length 1056.5
  Top Layer w6: U27.9@5374.02,1535.43 5492.13,1535.43 5541.34,1584.65 5541.34,1712.6 ; 5541.34,1714 5620.08,1792.74 5620.08,1879.92 5676.32,1936.17 5796.53,1936.17 5826.77,1905.92 5826.77,1811.02 5846.46,1791.34 5875.98,1791.34 5900.79,1766.54 5900.79,1712.6 J4.C23@5942.13,1671.26
PXI_AD4: J4.B23 U27.7 | length 1128.5
  Top Layer w6: v1(5305.12,1496.06) U27.7@5374.02,1496.06
  Bottom Layer w6: v1(5305.12,1496.06) 5305.12,1574.8 5600.39,1870.08 5718.5,1870.08 5738.19,1850.39 5738.19,1811.02 5757.87,1791.34 5816.93,1791.34 5826.77,1781.5 5974.41,1781.5 5984.25,1771.65 5984.25,1707.87 J4.B23@6020.87,1671.26
PXI_AD5: J4.E22 U27.6 | length 575.9
  Top Layer w6: U27.6@5374.02,1476.38 5452.76,1476.38 5679.13,1702.76 5718.5,1702.76 5743.31,1677.95 5743.31,1633.86 J4.E22@5784.65,1592.52
PXI_AD6: J4.D22 U27.5 | length 811.7
  Top Layer w6: v1(5305.12,1456.69) U27.5@5374.02,1456.69
  Bottom Layer w6: v1(5305.12,1456.69) 5561.02,1712.6 5728.35,1712.6 5748.03,1692.91 5748.03,1643.7 5767.72,1624.02 5816.93,1624.02 5848.43,1592.52 J4.D22@5863.39,1592.52
PXI_AD7: J4.A22 U27.4 | length 1164.1
  Top Layer w6: v1(5305.12,1417.32) 5324.8,1437.01 U27.4@5374.02,1437.01 ; v1(5565.94,1678.15) 5669.29,1781.5 5807.09,1781.5 5826.77,1761.81 5826.77,1653.54 5856.3,1624.02 6068.11,1624.02 J4.A22@6099.61,1592.52
  Bottom Layer w6: v1(5305.12,1417.32) v1(5565.94,1678.15)
PXI_AD8: J4.C21 U27.2 | length 730.6
  Top Layer w6: U27.2@5374.02,1397.64 5462.6,1397.64 5688.98,1624.02 5728.35,1624.02 5748.03,1604.33 5748.03,1564.96 5767.72,1545.28 5910.63,1545.28 J4.C21@5942.13,1513.78
PXI_AD9: J4.B21 U28.24 | length 1050.3
  Top Layer w6: U28.24@5374.02,1220.47 5423.23,1220.47 5482.28,1279.53 5482.28,1368.11 v1(5561.02,1446.85)
  Bottom Layer w6: v1(5561.02,1446.85) 5521.65,1486.22 5521.65,1535.43 5620.08,1633.86 5650.58,1633.86 5728.35,1633.86 5738.19,1624.02 5738.19,1584.65 5767.72,1555.12 5979.53,1555.12 J4.B21@6020.87,1513.78
PXI_AD10: J4.E20 U28.23 | length 682.5
  Top Layer w6: U28.23@5374.02,1200.79 5423.23,1200.79 5501.97,1279.53 5501.97,1338.58 5659.45,1496.06 5659.45,1525.59 5679.13,1545.28 5728.35,1545.28 5748.03,1525.59 5748.03,1471.65 J4.E20@5784.65,1435.04
PXI_AD11: J4.D20 U28.22 | length 651.9
  Top Layer w6: U28.22@5374.02,1181.1 5423.23,1181.1 5516.73,1274.61 5516.73,1313.98 v1(5561.02,1358.27)
  Bottom Layer w6: v1(5561.02,1358.27) 5679.13,1476.38 5787.4,1476.38 5826.77,1437.01 5861.42,1437.01 J4.D20@5863.39,1435.04
PXI_AD12: J4.A20 U28.21 | length 967.6
  Top Layer w6: U28.21@5374.02,1161.42 5423.23,1161.42 5531.5,1269.68 5531.5,1289.37 5583.17,1341.04 5602.85,1341.04 5659.45,1397.64 5659.45,1446.85 5679.13,1466.54 5728.35,1466.54 5748.03,1446.85 5748.03,1407.48 5767.72,1387.8 6033.46,1387.8 6080.71,1435.04 J4.A20@6099.61,1435.04
PXI_AD13: J4.E19 U28.20 | length 533.8
  Top Layer w6: U28.20@5374.02,1141.73 5423.23,1141.73 v1(5561.02,1279.53)
  Bottom Layer w6: v1(5561.02,1279.53) 5679.13,1397.64 5743.31,1397.64 J4.E19@5784.65,1356.3
PXI_AD14: J4.C19 U28.19 | length 754.8
  Top Layer w6: U28.19@5374.02,1122.05 5435.47,1122.05 5669.29,1355.87 5669.29,1368.11 5688.98,1387.8 5728.35,1387.8 5748.03,1368.11 5748.03,1338.58 5777.56,1309.06 5894.88,1309.06 J4.C19@5942.13,1356.3
PXI_AD15: J4.B19 U28.18 | length 752
  Top Layer w6: U28.18@5374.02,1102.36 5452.76,1102.36 v1(5561.02,1210.63)
  Bottom Layer w6: v1(5561.02,1210.63) 5669.29,1318.9 5983.46,1318.9 J4.B19@6020.87,1356.3
PXI_AD16: J4.C11 U28.3 | length 626
  Top Layer w6: U28.3@5374.02,807.09 5561.02,807.09 5590.55,836.61 5728.35,836.61 5787.4,777.56 5885.83,777.56 5937.01,726.38 J4.C11@5942.13,726.38
PXI_AD17: J4.B11 U28.4 | length 705.7
  Top Layer w6: U28.4@5374.02,826.77 5546.61,826.77 v1(5563.25,843.41)
  Bottom Layer w6: v1@5561.02,846.46 5738.19,846.46 5797.24,787.4 5959.84,787.4 J4.B11@6020.87,726.38
PXI_AD18: J4.A11 U28.5 | length 848.7
  Top Layer w6: U28.5@5374.02,846.46 5531.5,846.46 5600.39,915.35 5728.35,915.35 5748.03,935.04 5807.09,935.04 5935.04,807.09 6013.78,807.09 6094.49,726.38 J4.A11@6099.61,726.38
PXI_AD19: J4.E10 U29.24 | length 507.7
  Top Layer w6: U29.24@5374.02,610.24 5462.6,698.82 5551.18,698.82 v1(5590.55,659.45)
  Bottom Layer w6: v1(5590.55,659.45) 5649.61,600.39 5702.76,600.39 5750,647.64 J4.E10@5784.65,647.64
PXI_AD20: J4.D10 U29.23 | length 793.4
  Top Layer w6: v1(5295.28,590.55) U29.23@5374.02,590.55
  Bottom Layer w6: v1(5295.28,590.55) 5433.07,590.55 5600.39,757.87 5807.09,757.87 5816.93,748.03 5816.93,698.82 5863.39,652.36 J4.D10@5863.39,647.64
PXI_AD21: J4.A10 U29.22 | length 1162.1
  Top Layer w6: U29.22@5374.02,570.87 5442.91,570.87 5472.44,600.39 v1(5472.44,669.29)
  Bottom Layer w6: v1(5472.44,669.29) 5472.44,807.09 5590.55,925.2 5718.5,925.2 5738.19,944.88 5816.93,944.88 5944.88,816.93 5994.09,816.93 6053.15,757.87 6053.15,694.09 J4.A10@6099.61,647.64
PXI_AD22: J4.E9 U29.21 | length 794.3
  Top Layer w6: v1(5295.28,551.18) U29.21@5374.02,551.18
  Bottom Layer w6: v1(5295.28,551.18) 5433.07,551.18 5570.87,688.98 5807.09,688.98 5827.97,668.09 5827.97,612.22 J4.E9@5784.65,568.9
PXI_AD23: J4.A9 U29.20 | length 855.9
  Top Layer w6: U29.20@5374.02,531.5 5521.65,531.5 5666.48,676.32 6036.28,676.32 6062.99,649.61 6062.99,605.51 J4.A9@6099.61,568.9
PXI_AD24: J4.E8 U29.16 | length 452.2
  Top Layer w6: U29.16@5374.02,452.76 5561.02,452.76 5629.92,521.65 5728.35,521.65 5759.84,490.16 J4.E8@5784.65,490.16
PXI_AD25: J4.D8 U29.14 | length 521.2
  Top Layer w6: U29.14@5374.02,413.39 5590.55,413.39 5638.64,461.47 5798.09,461.47 5826.77,490.16 J4.D8@5863.39,490.16
PXI_AD26: J4.A8 U29.13 | length 960.6
  Top Layer w6: v1(5295.28,393.7) U29.13@5374.02,393.7
  Bottom Layer w6: v1(5295.28,393.7) 5590.55,393.7 5639.76,442.91 5708.66,442.91 5748.03,482.28 5748.03,501.97 5767.72,521.65 6068.11,521.65 J4.A8@6099.61,490.16
PXI_AD27: J4.E7 U29.12 | length 406.3
  Top Layer w6: U29.12@5374.02,374.02 5740.59,374.02 J4.E7@5768.7,402.13
PXI_AD28: J4.C7 U29.11 | length 792.6
  Top Layer w6: v1(5295.28,354.33) U29.11@5374.02,354.33
  Bottom Layer w6: v1(5295.28,354.33) 5600.39,354.33 5610.24,364.17 5718.5,364.17 5738.19,383.86 5738.19,413.39 5767.72,442.91 5910.63,442.91 J4.C7@5942.13,411.42
PXI_AD29: J4.B7 U29.10 | length 766.2
  Top Layer w6: U29.10@5374.02,334.65 5600.39,334.65 5639.76,295.28 5718.5,295.28 5734.59,311.36 5734.59,340.89 5767.72,374.02 5797.24,374.02 5826.77,403.54 5826.77,423.23 5846.46,442.91 5989.37,442.91 J4.B7@6020.87,411.42
PXI_AD30: J4.A7 U29.9 | length 982.1
  Top Layer w6: v1(5295.28,314.96) U29.9@5374.02,314.96
  Bottom Layer w6: v1(5295.28,314.96) 5610.24,314.96 5639.76,285.43 5728.35,285.43 5738.19,295.28 5738.19,354.33 5748.03,364.17 6052.36,364.17 J4.A7@6099.61,411.42
PXI_AD31: J4.E6 U29.7 | length 663
  Top Layer w6: v1(5295.28,275.59) U29.7@5374.02,275.59
  Bottom Layer w6: v1(5295.28,275.59) 5580.71,275.59 5631.34,224.96 5726.93,224.96 5738.19,236.22 5738.19,275.59 5784.65,322.05 J4.E6@5784.65,332.68
PXI_C/BE0: J4.E21 U27.3 | length 484.8
  Top Layer w6: U27.3@5374.02,1417.32 5442.91,1417.32 v1(5561.02,1535.43)
  Bottom Layer w6: v1(5561.02,1535.43) 5580.71,1555.12 5743.31,1555.12 J4.E21@5784.65,1513.78
PXI_C/BE1: J4.E18 U28.16 | length 525.6
  Top Layer w6: U28.16@5374.02,1062.99 5445.31,1062.99 5691.38,1309.06 5753.15,1309.06 J4.E18@5784.65,1277.56
PXI_C/BE2: J4.E11 U28.2 | length 435.9
  Top Layer w6: U28.2@5374.02,787.4 5580.71,787.4 5600.39,767.72 5743.31,767.72 J4.E11@5784.65,726.38
PXI_C/BE3: J4.C9 U29.18 | length 634.2
  Top Layer w6: U29.18@5374.02,492.13 5521.65,492.13 5639.76,610.24 5900.79,610.24 J4.C9@5942.13,568.9
PXI_CLK: J4.E5 U29.6 | length 450.6
  Top Layer w6: U29.6@5374.02,255.91 5551.18,255.91 5600.39,206.69 5737.4,206.69 J4.E5@5784.65,253.94
PXI_CLK10: J5.E17
PXI_DEVSEL: J4.A16 U28.10 | length 798.2
  Top Layer w6: U28.10@5374.02,944.88 5511.81,944.88 v1(5561.02,994.09)
  Bottom Layer w6: v1(5561.02,994.09) 5649.61,1082.68 6062.2,1082.68 J4.A16@6099.61,1120.08
PXI_FRAME: J4.B15 U28.6 | length 876.9
  Top Layer w6: v1(5295.28,866.14) U28.6@5374.02,866.14
  Bottom Layer w6: v1(5295.28,866.14) 5511.81,866.14 5583.56,937.89 5603.25,937.89 5659.45,994.09 5973.62,994.09 J4.B15@6020.87,1041.34
PXI_GNT: J4.D6 U29.4 | length 655.9
  Top Layer w6: U29.4@5379.19,211.36 5556.35,211.36 5639.76,127.95 5718.5,127.95 5738.19,147.64 5738.19,177.17 5767.72,206.69 5797.24,206.69 5816.93,226.38 5816.93,286.22 J4.D6@5863.39,332.68
PXI_IDSEL: J4.B9 U29.19 | length 828
  Top Layer w6: v1(5295.28,511.81) U29.19@5374.02,511.81
  Bottom Layer w6: v1(5295.28,511.81) 5639.76,511.81 5668.17,540.21 5992.18,540.21 J4.B9@6020.87,568.9
PXI_INTA: J4.A3 U29.2 | length 790.5
  Top Layer w6: U29.2@5374.02,177.17 5561.02,177.17 5679.13,59.06 6062.99,59.06 6099.61,95.67 J4.A3@6099.61,96.46
PXI_IRDY: J4.C15 U28.7 | length 632.5
  Top Layer w6: U28.7@5374.02,885.83 5511.81,885.83 5580.71,954.72 5600.39,954.72 5649.61,1003.94 5904.72,1003.94 J4.C15@5942.13,1041.34
PXI_PAR: J4.D18 U28.14 | length 594.6
  Top Layer w6: U28.14@5374.02,1023.62 5452.76,1023.62 v1(5561.02,1131.89)
  Bottom Layer w6: v1(5561.02,1131.89) 5669.29,1240.16 5825.98,1240.16 J4.D18@5863.39,1277.56
PXI_PERR: J4.E17 U28.12 | length 499.5
  Top Layer w6: U28.12@5374.02,984.25 5482.28,984.25 v1(5561.02,1062.99)
  Bottom Layer w6: v1(5561.02,1062.99) 5659.45,1161.42 5747.24,1161.42 J4.E17@5784.65,1198.82
PXI_REQ: J4.A6 U29.5 | length 1062.2
  Top Layer w6: v1(5295.28,236.22) U29.5@5374.02,236.22
  Bottom Layer w6: v1(5295.28,236.22) 5580.71,236.22 5679.13,137.8 5807.09,137.8 5816.93,147.64 5816.93,187.01 5836.61,206.69 5885.83,206.69 5895.67,216.54 5895.67,275.59 5905.51,285.43 6052.36,285.43 J4.A6@6099.61,332.68
PXI_RST: J4.C5 U29.3 | length 938.5
  Top Layer w6: v1(5295.28,196.85) U29.3@5374.02,196.85
  Bottom Layer w6: v1(5295.28,196.85) 5525.37,196.85 5669.29,52.93 5793.52,52.93 5826.77,86.18 5826.77,127.95 5836.61,137.8 5895.67,137.8 5905.51,147.64 5905.51,206.69 5942.13,243.31 J4.C5@5942.13,253.94 J4.C5@5946.85,253.94
PXI_SERR: J4.A18 U28.13 | length 838.9
  Top Layer w6: U28.13@5374.02,1003.94 5465,1003.94 5691.38,1230.32 6052.36,1230.32 J4.A18@6099.61,1277.56
PXI_START: J5.D17
PXI_STOP: J4.D16 U28.11 | length 579.9
  Top Layer w6: U28.11@5374.02,964.57 5494.53,964.57 5681.54,1151.57 5831.89,1151.57 J4.D16@5863.39,1120.08
PXI_TRDY: J4.E15 U28.9 | length 484.8
  Top Layer w6: U28.9@5374.02,925.2 5531.5,925.2 5679.13,1072.83 5753.15,1072.83 J4.E15@5784.65,1041.34
PXI_TRIG0: J5.B16
PXI_TRIG1: J5.A16
PXI_TRIG2: J5.A17
PXI_TRIG3: J5.A18
PXI_TRIG4: J5.B18
PXI_TRIG5: J5.C18
PXI_TRIG6: J5.E18
PXI_TRIG7: J5.E16
V16210: C120.2 C121.2 C123.2 D19.2 R116.2 U27.15 U28.15 U29.15 | length 1542.8
  Top Layer w10: v1(5265.75,1043.31) U28.15@5374.02,1043.31
  Top Layer w12: v1(5265.75,433.07) U29.15@5374.02,433.07 ; v1(5265.75,1653.54) U27.15@5374.02,1653.54
  Bottom Layer w10: v1@5259.84,1037.4 v1(5265.75,1043.31) ; C123.2@5259.84,1122.05 C123.2@5265.75,1116.14
  Bottom Layer w12: C121.2@5259.84,964.57 C120.2@5259.84,816.93 5259.84,438.98 v1(5265.75,433.07) ; C123.2@5259.84,1122.05 R116.2@5259.84,1417.32 D19.2@5259.84,1545.28 ; C121.2@5265.75,974.41 v1(5265.75,1043.31) C123.2@5265.75,1116.14 ; D19.2@5265.75,1551.18 v1(5265.75,1653.54)
VCCA_PLL1: C3.1 C5.2 C6.2 L1.2 U1.27 | length 499.8
  Top Layer w10: U1.27@3433.07,1318.9 v1(3513.78,1318.9)
  Bottom Layer w10: v1(3513.78,1318.9) 3568.9,1318.9 C6.2@3572.83,1322.83 C5.2@3671.26,1322.83 3917.32,1322.83 L1.2@3927.17,1312.99
VCCA_PLL2: C7.1 C9.2 C10.2 L2.2 U1.154 | length 515.6
  Top Layer w10: v1(4714.57,1309.06) 4724.41,1318.9 U1.154@4795.28,1318.9
  Bottom Layer w10: L2.2@4301.18,1312.99 C7.1@4446.85,1312.99 ; C7.1@4468.5,1309.06 4492.13,1332.68 C9.2@4557.09,1332.68 C10.2@4645.67,1332.68 ; C10.2@4659.45,1318.9 C10.2@4645.67,1332.68 ; v1(4714.57,1309.06) 4669.29,1309.06 C10.2@4645.67,1332.68
pads on no net: J1.101 J1.102 J4.A2 J4.A4 J4.A5 J4.A15 J4.A17 J4.A19 J4.A21 J4.A23 J4.B1 J4.B3 J4.B5 J4.B17 J4.B25 J4.C1 J4.C2 J4.C3 J4.C4 J4.C6 J4.C8 J4.C10 J4.C16 J4.C17 J4.C18 J4.C20 J4.C22 J4.C24 J4.C25 J4.D1 J4.D4 J4.D25 J4.E3 J4.E4 J4.E16 J4.E24 J4.F2 J4.F4 J4.F6 J4.F8 J4.F10 J4.F12 J4.F14 J4.F16 J4.F18 J4.F20 J4.F22 J4.F24 J5.A1 J5.A2 J5.A3 J5.A4 J5.A5 J5.A6 J5.A7 J5.A8 J5.A9 J5.A10 J5.A11 J5.A12 J5.A13 J5.A14 J5.A15 J5.A19 J5.A20 J5.A21 J5.A22 J5.B2 J5.B4 J5.B5 J5.B6 J5.B8 J5.B10 J5.B12 J5.B14 J5.B19 J5.B20 J5.B21 J5.B22 J5.C1 J5.C2 J5.C3 J5.C4 J5.C5 J5.C6 J5.C7 J5.C8 J5.C9 J5.C10 J5.C11 J5.C12 J5.C13 J5.C14 J5.C15 J5.C16 J5.C17 J5.C19 J5.C20 J5.C21 J5.C22 J5.D1 J5.D2 J5.D3 J5.D5 J5.D7 J5.D9 J5.D11 J5.D13 J5.D15 J5.D19 J5.D21 J5.D22 J5.E1 J5.E2 J5.E3 J5.E4 J5.E5 J5.E6 J5.E7 J5.E8 J5.E9 J5.E10 J5.E11 J5.E12 J5.E13 J5.E14 J5.E15 J5.E19 J5.E20 J5.E21 J5.E22 J5.F2 J5.F4 J5.F6 J5.F8 J5.F10 J5.F12 J5.F14 J5.F16 J5.F18 J5.F20 J5.F22 JP1.6 JP1.7 JP1.8 U1.19 U1.20 U1.21 U1.23 U1.32 U1.38 U1.39 U1.41 U1.42 U1.43 U1.44 U1.45 U1.46 U1.47 U1.48 U1.49 U1.50 U1.73 U1.74 U1.75 U1.76 U1.77 U1.78 U1.79 U1.82 U1.83 U1.84 U1.85 U1.86 U1.87 U1.93 U1.98 U1.106 U1.133 U1.152 U1.156 U1.168 U1.169 U1.170 U1.173 U1.174 U1.175 U1.176 U1.177 U1.178 U1.179 U1.180 U1.196 U1.197 U1.213 U1.226 U1.227 U1.228 U1.233 U1.234 U1.235 U1.236 U1.237 U1.238 U9.1 U10.1 U11.1 U12.1 U13.1 U14.1 U15.1 U16.1 U17.1 U18.1 U19.1 U20.1 U21.1 U22.1 U23.1 U24.1 U27.1 U27.13 U27.14 U27.16 U27.18 U27.19 U27.20 U27.21 U27.22 U27.23 U27.24 U27.25 U27.26 U27.27 U27.28 U27.29 U27.30 U27.31 U27.33 U27.34 U27.35 U28.1 U29.1 VR1.4 VR2.4 X1.1

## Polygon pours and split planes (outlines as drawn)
GND on Top Layer "Top Layer-No Net" (hatched 90Degree grid 0 track 10, remove dead copper, pour order 1000): -98.43,3690.94 -98.43,-167.32 -98.43,-187.01 6053.15,-187.01 6131.89,-108.27 6131.89,-98.43 6131.89,3631.89 6072.83,3690.94 6053.15,3690.94
GND on Bottom Layer "Top Layer-No Net" (hatched 90Degree grid 0 track 10, remove dead copper, pour order 1001): -98.43,3690.94 -98.43,-187.01 6053.15,-187.01 6131.89,-108.27 6131.89,3631.89 6072.83,3690.94

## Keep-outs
Keep-Out Layer:
  lines w7.87: -140.55,-218.5 6079.92,-218.5 6158.66,-139.76 6158.66,3642.05 6082.2,3718.5 -140.55,3718.5 -140.55,-218.5

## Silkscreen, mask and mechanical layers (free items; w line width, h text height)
Top Overlay:
  text "5V" at 4596.46,3592.05 h40
  text "5V DC" at 4888.78,3021.65 h70
  text "1.5V" at 4596.46,2972.44 h40
  text "5V Out" at 423.23,2962.6 h70 r90
  text "3.3V" at 5423.23,2962.05 h40
  text "5V OC" at 4583.66,2805.12 h70
  text "27V Out" at 423.23,2222.05 h70 r90
  text "5V In" at 541.34,1222.05 h70 r90
  text "Byte Blaster" at 2854.33,688.98 h70 r90
  text "27V In" at 533.66,216.54 h70 r90
  text "JTAG" at 2864.17,82.05 h70 r90
  text "SCSI-100" at 265.75,-7.95 h70

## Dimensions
-140.55,-218.5 to 6158.66,-120.08 on Mechanical 13
-140.55,-218.5 to -140.55,3718.5 on Mechanical 13
0,0 to 0,3500 on Mechanical 13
